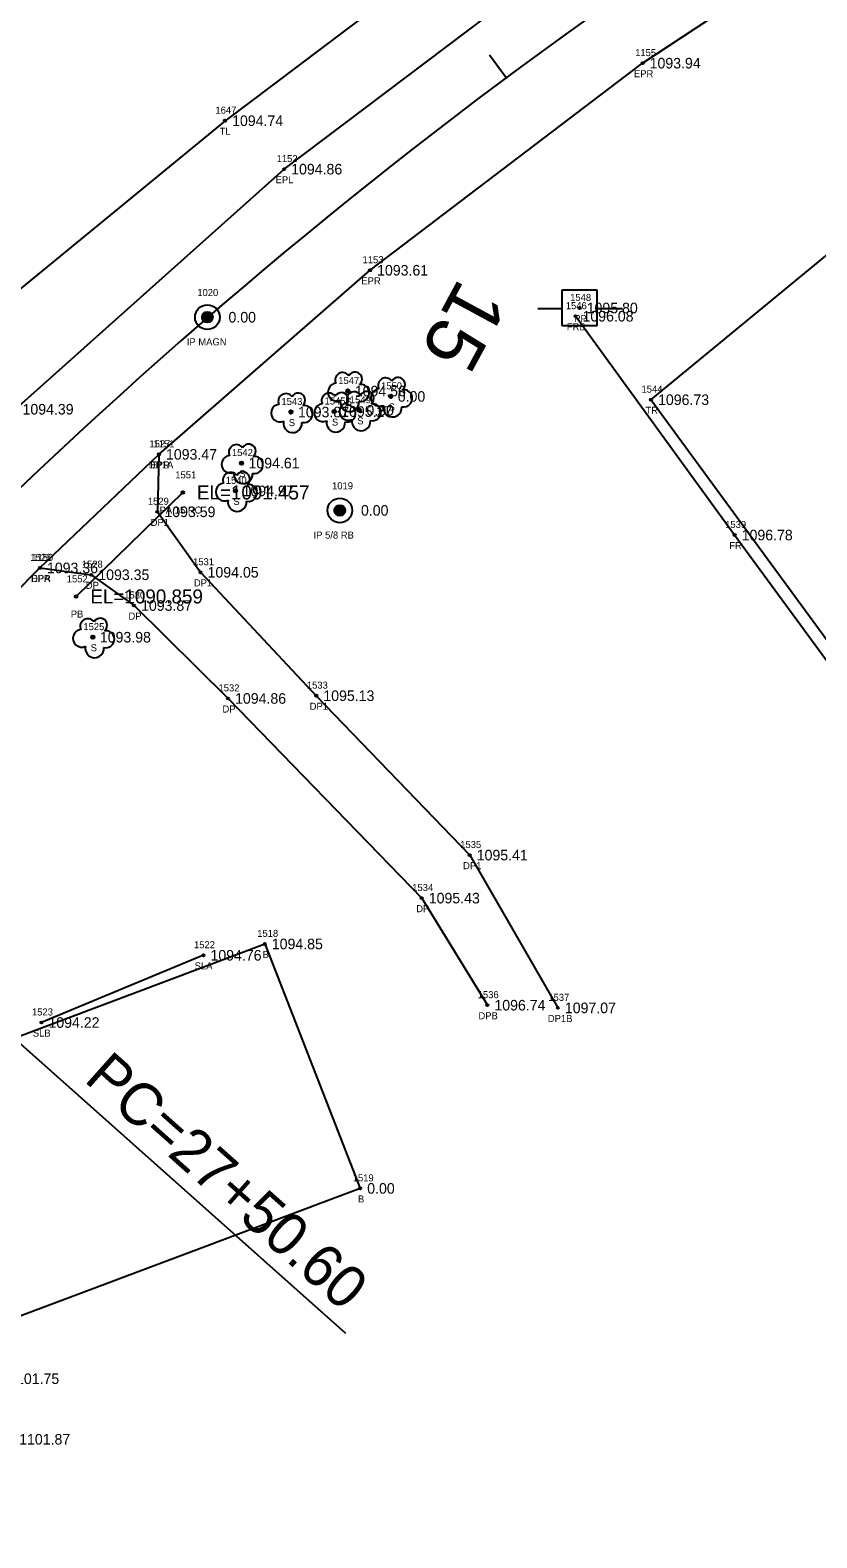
# Model space of a CAD drawing. Extents: x 1539151 to 1541799, y 1198646 to 1201165.
# Drawn here: x 1540843.3 to 1540955, y 1200081.3 to 1200295.5 of the extents above; entities that cross this region are included whole.
import ezdxf

# ---------------------------------------------------------------- set-up
doc = ezdxf.new("R2010")
doc.units = 0
for name, color, linetype in [('RD_EX_Bldg', 7, 'Continuous'), ('RD_EX_Bldg_txCode', 7, 'Continuous'), ('RD_EX_DR_Pipe', 7, 'Continuous'), ('RD_EX_DR_Pipe_txCode', 7, 'Continuous'), ('RD_EX_Driveway', 7, 'Continuous'), ('RD_EX_Driveway_txCode', 7, 'Continuous'), ('RD_EX_DV_Prop_txCode', 7, 'Continuous'), ('RD_EX_DV_PropPin', 7, 'Continuous'), ('RD_EX_Fence_Other', 7, 'Continuous'), ('RD_EX_Fence_Other_txCode', 7, 'Continuous'), ('RD_EX_Road', 7, 'Continuous'), ('RD_EX_Road_txCode', 7, 'Continuous'), ('RD_EX_TX_Bldg_ELEV', 7, 'Continuous'), ('RD_EX_TX_Driveway_ELEV', 7, 'Continuous'), ('RD_EX_TX_DV_Prop_ELEV', 7, 'Continuous'), ('RD_EX_TX_Fence_Other_ELEV', 7, 'Continuous'), ('RD_EX_TX_Road_ELEV', 7, 'Continuous'), ('RD_EX_TX_VEG_ELEV', 7, 'Continuous'), ('RD_EX_UT', 7, 'Continuous'), ('RD_EX_UT_txCode', 7, 'Continuous'), ('RD_EX_VEG', 7, 'Continuous'), ('RD_EX_VEG_txCode', 7, 'Continuous'), ('RD_HC_Cl', 7, 'Continuous'), ('RD_HC_Data', 7, 'Continuous'), ('RD_HC_Data_Tic', 7, 'Continuous'), ('RD_HC_Survey_ELEV', 7, 'Continuous'), ('RD_HC_TX_Sta50', 7, 'Continuous'), ('RD_SMD_Locator', 7, 'Continuous'), ('RD_TX_Pipe_ElevEX', 7, 'Continuous')]:
    doc.layers.add(name, color=color, linetype=linetype)

msp = doc.modelspace()

# ---------------------------------------------------------------- linework, layer by layer
at = {"layer": 'RD_EX_Bldg'}
msp.add_lwpolyline([(1540835.02, 1200110.24), (1540821.46, 1200144.96), (1540876.62, 1200165.68), (1540890.17, 1200130.96), (1540835.02, 1200110.24)], dxfattribs=at)
at = {"layer": 'RD_EX_DR_Pipe'}
msp.add_line((1540864.98, 1200229.81), (1540849.85, 1200215.04), dxfattribs=at)
at = {"layer": 'RD_EX_Driveway'}
for points in [[(1540861.59, 1200235.22), (1540861.37, 1200227.06), (1540867.5, 1200218.47), (1540883.94, 1200200.94), (1540905.72, 1200178.3), (1540918.24, 1200156.6)], [(1540844.69, 1200219.09), (1540851.98, 1200218.12), (1540858.05, 1200213.75), (1540871.4, 1200200.55), (1540898.91, 1200172.19), (1540908.23, 1200156.98)]]:
    msp.add_lwpolyline(points, dxfattribs=at)
at = {"layer": 'RD_EX_DV_PropPin'}
for p, q in [((1540867.73, 1200254.51), (1540867.73, 1200254.9)), ((1540867.77, 1200254.41), (1540867.77, 1200255)), ((1540867.8, 1200254.33), (1540867.8, 1200255.07)), ((1540867.84, 1200254.28), (1540867.84, 1200255.13)), ((1540867.87, 1200254.23), (1540867.87, 1200255.18)), ((1540867.91, 1200254.19), (1540867.91, 1200255.22)), ((1540867.94, 1200254.15), (1540867.94, 1200255.25)), ((1540867.98, 1200254.12), (1540867.98, 1200255.29)), ((1540868.01, 1200254.09), (1540868.01, 1200255.31)), ((1540868.05, 1200254.07), (1540868.05, 1200255.34)), ((1540868.08, 1200254.05), (1540868.08, 1200255.36)), ((1540868.12, 1200254.03), (1540868.12, 1200255.38)), ((1540868.15, 1200254.01), (1540868.15, 1200255.4)), ((1540868.19, 1200254), (1540868.19, 1200255.41)), ((1540868.22, 1200253.98), (1540868.22, 1200255.42)), ((1540868.26, 1200253.97), (1540868.26, 1200255.44)), ((1540868.29, 1200253.96), (1540868.29, 1200255.44)), ((1540868.33, 1200253.96), (1540868.33, 1200255.45)), ((1540868.36, 1200253.95), (1540868.36, 1200255.46)), ((1540868.4, 1200253.95), (1540868.4, 1200255.46)), ((1540868.43, 1200253.94), (1540868.43, 1200255.46)), ((1540868.47, 1200253.94), (1540868.47, 1200255.46)), ((1540868.5, 1200253.94), (1540868.5, 1200255.46)), ((1540868.54, 1200253.95), (1540868.54, 1200255.46)), ((1540868.57, 1200253.95), (1540868.57, 1200255.46)), ((1540868.61, 1200253.96), (1540868.61, 1200255.45)), ((1540868.64, 1200253.96), (1540868.64, 1200255.44)), ((1540868.68, 1200253.97), (1540868.68, 1200255.44)), ((1540868.71, 1200253.98), (1540868.71, 1200255.42)), ((1540868.75, 1200254), (1540868.75, 1200255.41)), ((1540868.78, 1200254.01), (1540868.78, 1200255.4)), ((1540868.82, 1200254.03), (1540868.82, 1200255.38)), ((1540868.85, 1200254.05), (1540868.85, 1200255.36)), ((1540868.89, 1200254.07), (1540868.89, 1200255.34)), ((1540868.92, 1200254.09), (1540868.92, 1200255.31)), ((1540868.96, 1200254.12), (1540868.96, 1200255.29)), ((1540868.99, 1200254.15), (1540868.99, 1200255.25)), ((1540869.03, 1200254.19), (1540869.03, 1200255.22)), ((1540869.06, 1200254.23), (1540869.06, 1200255.18)), ((1540869.1, 1200254.28), (1540869.1, 1200255.13)), ((1540869.13, 1200254.33), (1540869.13, 1200255.07)), ((1540869.17, 1200254.41), (1540869.17, 1200255)), ((1540869.2, 1200254.51), (1540869.2, 1200254.9)), ((1540886.54, 1200227.07), (1540886.54, 1200227.46)), ((1540886.58, 1200226.97), (1540886.58, 1200227.56)), ((1540886.61, 1200226.89), (1540886.61, 1200227.63)), ((1540886.65, 1200226.84), (1540886.65, 1200227.69)), ((1540886.68, 1200226.79), (1540886.68, 1200227.74)), ((1540886.72, 1200226.75), (1540886.72, 1200227.78)), ((1540886.75, 1200226.71), (1540886.75, 1200227.81)), ((1540886.79, 1200226.68), (1540886.79, 1200227.85)), ((1540886.82, 1200226.65), (1540886.82, 1200227.87)), ((1540886.86, 1200226.63), (1540886.86, 1200227.9)), ((1540886.89, 1200226.61), (1540886.89, 1200227.92)), ((1540886.93, 1200226.59), (1540886.93, 1200227.94)), ((1540886.96, 1200226.57), (1540886.96, 1200227.96)), ((1540887, 1200226.56), (1540887, 1200227.97)), ((1540887.03, 1200226.54), (1540887.03, 1200227.98)), ((1540887.07, 1200226.53), (1540887.07, 1200227.99)), ((1540887.1, 1200226.52), (1540887.1, 1200228)), ((1540887.14, 1200226.52), (1540887.14, 1200228.01)), ((1540887.17, 1200226.51), (1540887.17, 1200228.02)), ((1540887.21, 1200226.51), (1540887.21, 1200228.02)), ((1540887.24, 1200226.5), (1540887.24, 1200228.02)), ((1540887.28, 1200226.5), (1540887.28, 1200228.02)), ((1540887.31, 1200226.5), (1540887.31, 1200228.02)), ((1540887.35, 1200226.51), (1540887.35, 1200228.02)), ((1540887.38, 1200226.51), (1540887.38, 1200228.02)), ((1540887.42, 1200226.52), (1540887.42, 1200228.01)), ((1540887.45, 1200226.52), (1540887.45, 1200228)), ((1540887.49, 1200226.53), (1540887.49, 1200227.99)), ((1540887.52, 1200226.54), (1540887.52, 1200227.98)), ((1540887.56, 1200226.56), (1540887.56, 1200227.97)), ((1540887.59, 1200226.57), (1540887.59, 1200227.96)), ((1540887.63, 1200226.59), (1540887.63, 1200227.94)), ((1540887.66, 1200226.61), (1540887.66, 1200227.92)), ((1540887.7, 1200226.63), (1540887.7, 1200227.9)), ((1540887.73, 1200226.65), (1540887.73, 1200227.87)), ((1540887.77, 1200226.68), (1540887.77, 1200227.85)), ((1540887.8, 1200226.71), (1540887.8, 1200227.81)), ((1540887.84, 1200226.75), (1540887.84, 1200227.78)), ((1540887.87, 1200226.79), (1540887.87, 1200227.74)), ((1540887.91, 1200226.84), (1540887.91, 1200227.69)), ((1540887.94, 1200226.89), (1540887.94, 1200227.63)), ((1540887.98, 1200226.97), (1540887.98, 1200227.56)), ((1540888.01, 1200227.07), (1540888.01, 1200227.46))]:
    msp.add_line(p, q, dxfattribs=at)
for centre, radius in [((1540868.47, 1200254.7), 1.75), ((1540868.47, 1200254.7), 0.761), ((1540887.28, 1200227.26), 1.75), ((1540887.28, 1200227.26), 0.761)]:
    msp.add_circle(centre, radius, dxfattribs=at)
at = {"layer": 'RD_EX_Fence_Other'}
msp.add_lwpolyline([(1540968.19, 1200189.83), (1540943.35, 1200223.76), (1540920.74, 1200254.84)], dxfattribs=at)
at = {"layer": 'RD_EX_Road'}
for points in [[(1540705.32, 1200094.04), (1540739.01, 1200131.56), (1540770.5, 1200167.37), (1540805.54, 1200205.85), (1540841.22, 1200241.63), (1540879.37, 1200275.73), (1540919.79, 1200306.26), (1540962.73, 1200334.43), (1541008.04, 1200359.97), (1541051.86, 1200381.29), (1541099.37, 1200400.02), (1541147.99, 1200415.01), (1541197.22, 1200426.76), (1541247.29, 1200435.81)], [(1540718.68, 1200081.33), (1540762.24, 1200130.19), (1540779.72, 1200149.92), (1540818.99, 1200193.09), (1540844.69, 1200219.09), (1540861.59, 1200235.22), (1540891.57, 1200261.37), (1540930.28, 1200290.78), (1540971.82, 1200318.2), (1541015.09, 1200342.79), (1541060.36, 1200364.79), (1541076.53, 1200371.56), (1541099.1, 1200380.09), (1541153.21, 1200396.86), (1541201.21, 1200408.64), (1541249.91, 1200417.32)]]:
    msp.add_lwpolyline(points, dxfattribs=at)
at = {"layer": 'RD_EX_UT'}
for p, q in [((1540923.83, 1200258.52), (1540918.83, 1200258.52)), ((1540918.83, 1200258.52), (1540918.83, 1200253.52)), ((1540923.83, 1200253.52), (1540923.83, 1200258.52)), ((1540915.4, 1200255.96), (1540918.87, 1200255.96)), ((1540923.76, 1200255.96), (1540927.4, 1200255.96)), ((1540918.83, 1200253.52), (1540923.83, 1200253.52))]:
    msp.add_line(p, q, dxfattribs=at)
at = {"layer": 'RD_EX_VEG'}
msp.add_line((1540867.91, 1200164.07), (1540844.9, 1200154.52), dxfattribs=at)
for points in [[(1541184.89, 1200430.38), (1541110.91, 1200418.83), (1540957.41, 1200347.72), (1540870.98, 1200282.61), (1540802.21, 1200226.22), (1540781.04, 1200235.77)], [(1540970.04, 1200190.25), (1540931.47, 1200242.98), (1540974.48, 1200278.36), (1541008.82, 1200224.19), (1541121.72, 1200285)]]:
    msp.add_lwpolyline(points, dxfattribs=at)
for centre in [(1540888.41, 1200244.21), (1540890.06, 1200241.48), (1540894.51, 1200243.45), (1540880.34, 1200241.23), (1540886.47, 1200241.3), (1540873.31, 1200233.98), (1540872.47, 1200230.03), (1540852.2, 1200209.25)]:
    msp.add_circle(centre, 0.25, dxfattribs=at)
for centre, radius, start, end in [((1540887.69, 1200245.76), 1.08, 34.9763, 204.756), ((1540889.46, 1200245.91), 0.995, 308.7626, 152.0467), ((1540893.79, 1200245), 1.08, 34.9763, 204.756), ((1540895.56, 1200245.15), 0.995, 308.7626, 152.0467), ((1540879.62, 1200242.77), 1.08, 34.9763, 204.756), ((1540881.38, 1200242.93), 0.995, 308.7626, 152.0467), ((1540885.75, 1200242.84), 1.08, 34.9763, 204.756), ((1540886.85, 1200244.06), 1.26, 96.4518, 294.734), ((1540887.51, 1200243), 0.995, 308.7626, 152.0467), ((1540889.34, 1200243.03), 1.08, 34.9763, 204.756), ((1540890.25, 1200243.93), 1.22, 256.5667, 98.1046), ((1540891.11, 1200243.18), 0.995, 308.7626, 152.0467), ((1540892.95, 1200243.29), 1.26, 96.4518, 294.734), ((1540896.35, 1200243.17), 1.22, 256.5667, 98.1046), ((1540878.78, 1200241.07), 1.26, 96.4518, 294.734), ((1540882.18, 1200240.95), 1.22, 256.5667, 98.1046), ((1540884.9, 1200241.14), 1.26, 96.4518, 294.734), ((1540888.5, 1200241.32), 1.26, 96.4518, 294.734), ((1540888.66, 1200242.61), 1.32, 166.8827, 5.7589), ((1540888.31, 1200241.02), 1.22, 256.5667, 98.1046), ((1540891.9, 1200241.2), 1.22, 256.5667, 98.1046), ((1540894.76, 1200241.85), 1.32, 166.8827, 5.7589), ((1540880.58, 1200239.63), 1.32, 166.8827, 5.7589), ((1540886.71, 1200239.7), 1.32, 166.8827, 5.7589), ((1540890.31, 1200239.88), 1.32, 166.8827, 5.7589), ((1540872.59, 1200235.52), 1.08, 34.9763, 204.756), ((1540874.36, 1200235.68), 0.995, 308.7626, 152.0467), ((1540871.75, 1200233.82), 1.26, 96.4518, 294.734), ((1540875.15, 1200233.7), 1.22, 256.5667, 98.1046), ((1540870.91, 1200229.87), 1.26, 96.4518, 294.734), ((1540871.75, 1200231.58), 1.08, 34.9763, 204.756), ((1540873.56, 1200232.38), 1.32, 166.8827, 5.7589), ((1540873.51, 1200231.73), 0.995, 308.7626, 152.0467), ((1540874.31, 1200229.75), 1.22, 256.5667, 98.1046), ((1540872.71, 1200228.43), 1.32, 166.8827, 5.7589), ((1540851.48, 1200210.8), 1.08, 34.9763, 204.756), ((1540853.25, 1200210.95), 0.995, 308.7626, 152.0467), ((1540850.64, 1200209.1), 1.26, 96.4518, 294.734), ((1540854.04, 1200208.97), 1.22, 256.5667, 98.1046), ((1540852.45, 1200207.65), 1.32, 166.8827, 5.7589)]:
    msp.add_arc(centre, radius, start, end, dxfattribs=at)
at = {"layer": 'RD_HC_Cl'}
msp.add_arc((1541347.27, 1199701.68), 731.44, 99.31232, 138.32753, dxfattribs=at)
at = {"layer": 'RD_HC_Data'}
msp.add_line((1540800.92, 1200188), (1540888.08, 1200110.41), dxfattribs=at)
at = {"layer": 'RD_HC_Data_Tic'}
msp.add_line((1540910.92, 1200288.71), (1540908.54, 1200291.92), dxfattribs=at)
at = {"layer": 'RD_SMD_Locator'}
for centre, radius in [((1540930.28, 1200290.78), 0.15), ((1540870.98, 1200282.61), 0.15), ((1540879.37, 1200275.73), 0.15), ((1540891.57, 1200261.37), 0.15), ((1540868.47, 1200254.7), 0.15), ((1540920.74, 1200254.84), 0.15), ((1540921.34, 1200256.01), 0.15), ((1540888.41, 1200244.21), 0.15), ((1540894.51, 1200243.45), 0.15), ((1540931.47, 1200242.98), 0.15), ((1540880.34, 1200241.23), 0.15), ((1540886.47, 1200241.3), 0.15), ((1540890.06, 1200241.48), 0.15), ((1540861.59, 1200235.22), 0.15), ((1540861.59, 1200235.22), 0.15), ((1540873.31, 1200233.98), 0.15), ((1540864.98, 1200229.81), 0.2), ((1540872.47, 1200230.03), 0.15), ((1540861.37, 1200227.06), 0.15), ((1540887.28, 1200227.26), 0.15), ((1540943.35, 1200223.76), 0.15), ((1540844.69, 1200219.09), 0.15), ((1540844.69, 1200219.09), 0.15), ((1540851.98, 1200218.12), 0.15), ((1540867.5, 1200218.47), 0.15), ((1540849.85, 1200215.04), 0.2), ((1540858.05, 1200213.75), 0.15), ((1540852.2, 1200209.25), 0.15), ((1540883.94, 1200200.94), 0.15), ((1540871.4, 1200200.55), 0.15), ((1540905.72, 1200178.3), 0.15), ((1540898.91, 1200172.19), 0.15), ((1540876.62, 1200165.68), 0.15), ((1540867.91, 1200164.07), 0.15), ((1540908.23, 1200156.98), 0.15), ((1540918.24, 1200156.6), 0.15), ((1540844.9, 1200154.52), 0.15), ((1540890.17, 1200130.96), 0.15)]:
    msp.add_circle(centre, radius, dxfattribs=at)

# ---------------------------------------------------------------- texts
at = {"layer": 'RD_EX_Bldg_txCode'}
for s, p in [('1518', (1540875.55, 1200166.68)), ('B', (1540876.31, 1200163.68)), ('1519', (1540889.11, 1200131.96)), ('B', (1540889.86, 1200128.96))]:
    msp.add_text(s, height=1, dxfattribs=at).set_placement(p)
at = {"layer": 'RD_EX_DR_Pipe_txCode'}
for s, p in [('1551', (1540863.91, 1200231.81)), ('PA 15 RC', (1540861.68, 1200226.81)), ('1552', (1540848.5, 1200217.04)), ('PB', (1540849.07, 1200212.04))]:
    msp.add_text(s, height=1, dxfattribs=at).set_placement(p)
at = {"layer": 'RD_EX_Driveway_txCode'}
for s, p in [('1527', (1540860.24, 1200236.22)), ('DP1A', (1540860.15, 1200233.22)), ('1529', (1540860.02, 1200228.06)), ('DP1', (1540860.42, 1200225.06)), ('1526', (1540843.32, 1200220.09)), ('1531', (1540866.44, 1200219.47)), ('1528', (1540850.64, 1200219.12)), ('DPA', (1540843.43, 1200217.09)), ('DP', (1540851.21, 1200216.12)), ('DP1', (1540866.55, 1200216.47)), ('1530', (1540856.66, 1200214.75)), ('DP', (1540857.27, 1200211.75)), ('1532', (1540870.05, 1200201.55)), ('1533', (1540882.6, 1200201.94)), ('DP', (1540870.62, 1200198.55)), ('DP1', (1540883, 1200198.94)), ('1535', (1540904.38, 1200179.3)), ('DP1', (1540904.78, 1200176.3)), ('1534', (1540897.56, 1200173.19)), ('DP', (1540898.13, 1200170.19)), ('1536', (1540906.86, 1200157.98)), ('1537', (1540916.89, 1200157.6)), ('DPB', (1540906.97, 1200154.98)), ('DP1B', (1540916.82, 1200154.6))]:
    msp.add_text(s, height=1, dxfattribs=at).set_placement(p)
at = {"layer": 'RD_EX_DV_Prop_txCode'}
for s, p in [('1020', (1540867.04, 1200257.7)), ('IP MAGN', (1540865.55, 1200250.7)), ('1019', (1540886.18, 1200230.26)), ('IP 5/8 RB', (1540883.55, 1200223.26))]:
    msp.add_text(s, height=1, dxfattribs=at).set_placement(p)
at = {"layer": 'RD_EX_Fence_Other_txCode'}
for s, p in [('1546', (1540919.37, 1200255.84)), ('FRB', (1540919.52, 1200252.84)), ('1539', (1540942, 1200224.76)), ('FR', (1540942.59, 1200221.76))]:
    msp.add_text(s, height=1, dxfattribs=at).set_placement(p)
at = {"layer": 'RD_EX_Road_txCode'}
for s, p in [('1155', (1540929.22, 1200291.78)), ('EPR', (1540929.05, 1200288.78)), ('1152', (1540878.3, 1200276.73)), ('EPL', (1540878.16, 1200273.73)), ('1153', (1540890.51, 1200262.37)), ('EPR', (1540890.34, 1200259.37)), ('1151', (1540860.81, 1200236.22)), ('EPR', (1540860.36, 1200233.22)), ('1150', (1540843.59, 1200220.09)), ('EPR', (1540843.47, 1200217.09))]:
    msp.add_text(s, height=1, dxfattribs=at).set_placement(p)
at = {"layer": 'RD_EX_TX_Bldg_ELEV'}
for s, p in [('1094.85', (1540877.62, 1200164.93)), ('0.00', (1540891.17, 1200130.21))]:
    msp.add_text(s, height=1.5, dxfattribs=at).set_placement(p)
at = {"layer": 'RD_EX_TX_Driveway_ELEV'}
for s, p in [('1093.47', (1540862.59, 1200234.47)), ('1093.59', (1540862.37, 1200226.31)), ('1093.36', (1540845.69, 1200218.34)), ('1093.35', (1540852.98, 1200217.37)), ('1094.05', (1540868.5, 1200217.72)), ('1093.87', (1540859.05, 1200213)), ('1094.86', (1540872.4, 1200199.8)), ('1095.13', (1540884.94, 1200200.19)), ('1095.41', (1540906.72, 1200177.55)), ('1095.43', (1540899.91, 1200171.44)), ('1096.74', (1540909.23, 1200156.23)), ('1097.07', (1540919.24, 1200155.85)), ('1101.75', (1540840.18, 1200103.18)), ('1101.87', (1540841.74, 1200094.58))]:
    msp.add_text(s, height=1.5, dxfattribs=at).set_placement(p)
at = {"layer": 'RD_EX_TX_DV_Prop_ELEV'}
for p in [(1540871.47, 1200253.95), (1540890.28, 1200226.51)]:
    msp.add_text('0.00', height=1.5, dxfattribs=at).set_placement(p)
at = {"layer": 'RD_EX_TX_Fence_Other_ELEV'}
for s, p in [('1096.08', (1540921.74, 1200254.09)), ('1096.78', (1540944.35, 1200223.01))]:
    msp.add_text(s, height=1.5, dxfattribs=at).set_placement(p)
at = {"layer": 'RD_EX_TX_Road_ELEV'}
for s, p in [('1093.94', (1540931.28, 1200290.03)), ('1094.86', (1540880.37, 1200274.98)), ('1093.61', (1540892.57, 1200260.62)), ('1094.39', (1540842.22, 1200240.88)), ('1093.47', (1540862.59, 1200234.47)), ('1093.36', (1540845.69, 1200218.34))]:
    msp.add_text(s, height=1.5, dxfattribs=at).set_placement(p)
at = {"layer": 'RD_EX_TX_VEG_ELEV'}
for s, p in [('1094.74', (1540871.98, 1200281.86)), ('1094.56', (1540889.41, 1200243.46)), ('0.00', (1540895.51, 1200242.7)), ('1093.87', (1540881.34, 1200240.48)), ('1095.27', (1540887.47, 1200240.55)), ('0.00', (1540891.06, 1200240.73)), ('1096.73', (1540932.47, 1200242.23)), ('1094.61', (1540874.31, 1200233.23)), ('1094.97', (1540873.47, 1200229.28)), ('1093.98', (1540853.2, 1200208.5)), ('1094.76', (1540868.91, 1200163.32)), ('1094.22', (1540845.9, 1200153.77))]:
    msp.add_text(s, height=1.5, dxfattribs=at).set_placement(p)
at = {"layer": 'RD_EX_UT_txCode'}
for s, p in [('1548', (1540919.99, 1200257.01)), ('PP', (1540920.56, 1200254.01))]:
    msp.add_text(s, height=1, dxfattribs=at).set_placement(p)
at = {"layer": 'RD_EX_VEG_txCode'}
for s, p in [('1647', (1540869.61, 1200283.61)), ('TL', (1540870.21, 1200280.61)), ('1547', (1540887.06, 1200245.21)), ('1550', (1540893.13, 1200244.45)), ('1544', (1540930.12, 1200243.98)), ('1543', (1540878.99, 1200242.23)), ('1545', (1540885.12, 1200242.3)), ('S', (1540888.1, 1200242.21)), ('1549', (1540888.71, 1200242.48)), ('S', (1540894.21, 1200241.45)), ('TR', (1540930.68, 1200240.98)), ('S', (1540880.03, 1200239.23)), ('S', (1540886.16, 1200239.3)), ('S', (1540889.75, 1200239.48)), ('1542', (1540871.96, 1200234.98)), ('1540', (1540871.08, 1200231.03)), ('S', (1540873, 1200231.98)), ('S', (1540872.16, 1200228.03)), ('1525', (1540850.86, 1200210.25)), ('S', (1540851.9, 1200207.25)), ('1522', (1540866.57, 1200165.07)), ('SLA', (1540866.67, 1200162.07)), ('1523', (1540843.56, 1200155.52)), ('SLB', (1540843.68, 1200152.52))]:
    msp.add_text(s, height=1, dxfattribs=at).set_placement(p)
at = {"layer": 'RD_HC_Data'}
msp.add_text('PC=27+50.60', height=6, rotation=318.3275, dxfattribs=at).set_placement((1540850.8, 1200146.27))
at = {"layer": 'RD_HC_Survey_ELEV'}
msp.add_text('1095.80', height=1.5, dxfattribs=at).set_placement((1540922.34, 1200255.26))
at = {"layer": 'RD_HC_TX_Sta50'}
msp.add_text('15', height=8, rotation=241.5754, dxfattribs=at).set_placement((1540904.28, 1200260.49))
at = {"layer": 'RD_TX_Pipe_ElevEX'}
for s, p in [('EL=1091.457', (1540866.98, 1200228.81)), ('EL=1090.859', (1540851.85, 1200214.04))]:
    msp.add_text(s, height=2, dxfattribs=at).set_placement(p)

doc.saveas('drawing.dxf')
